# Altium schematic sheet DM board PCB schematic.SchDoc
size 386 x 246 mm
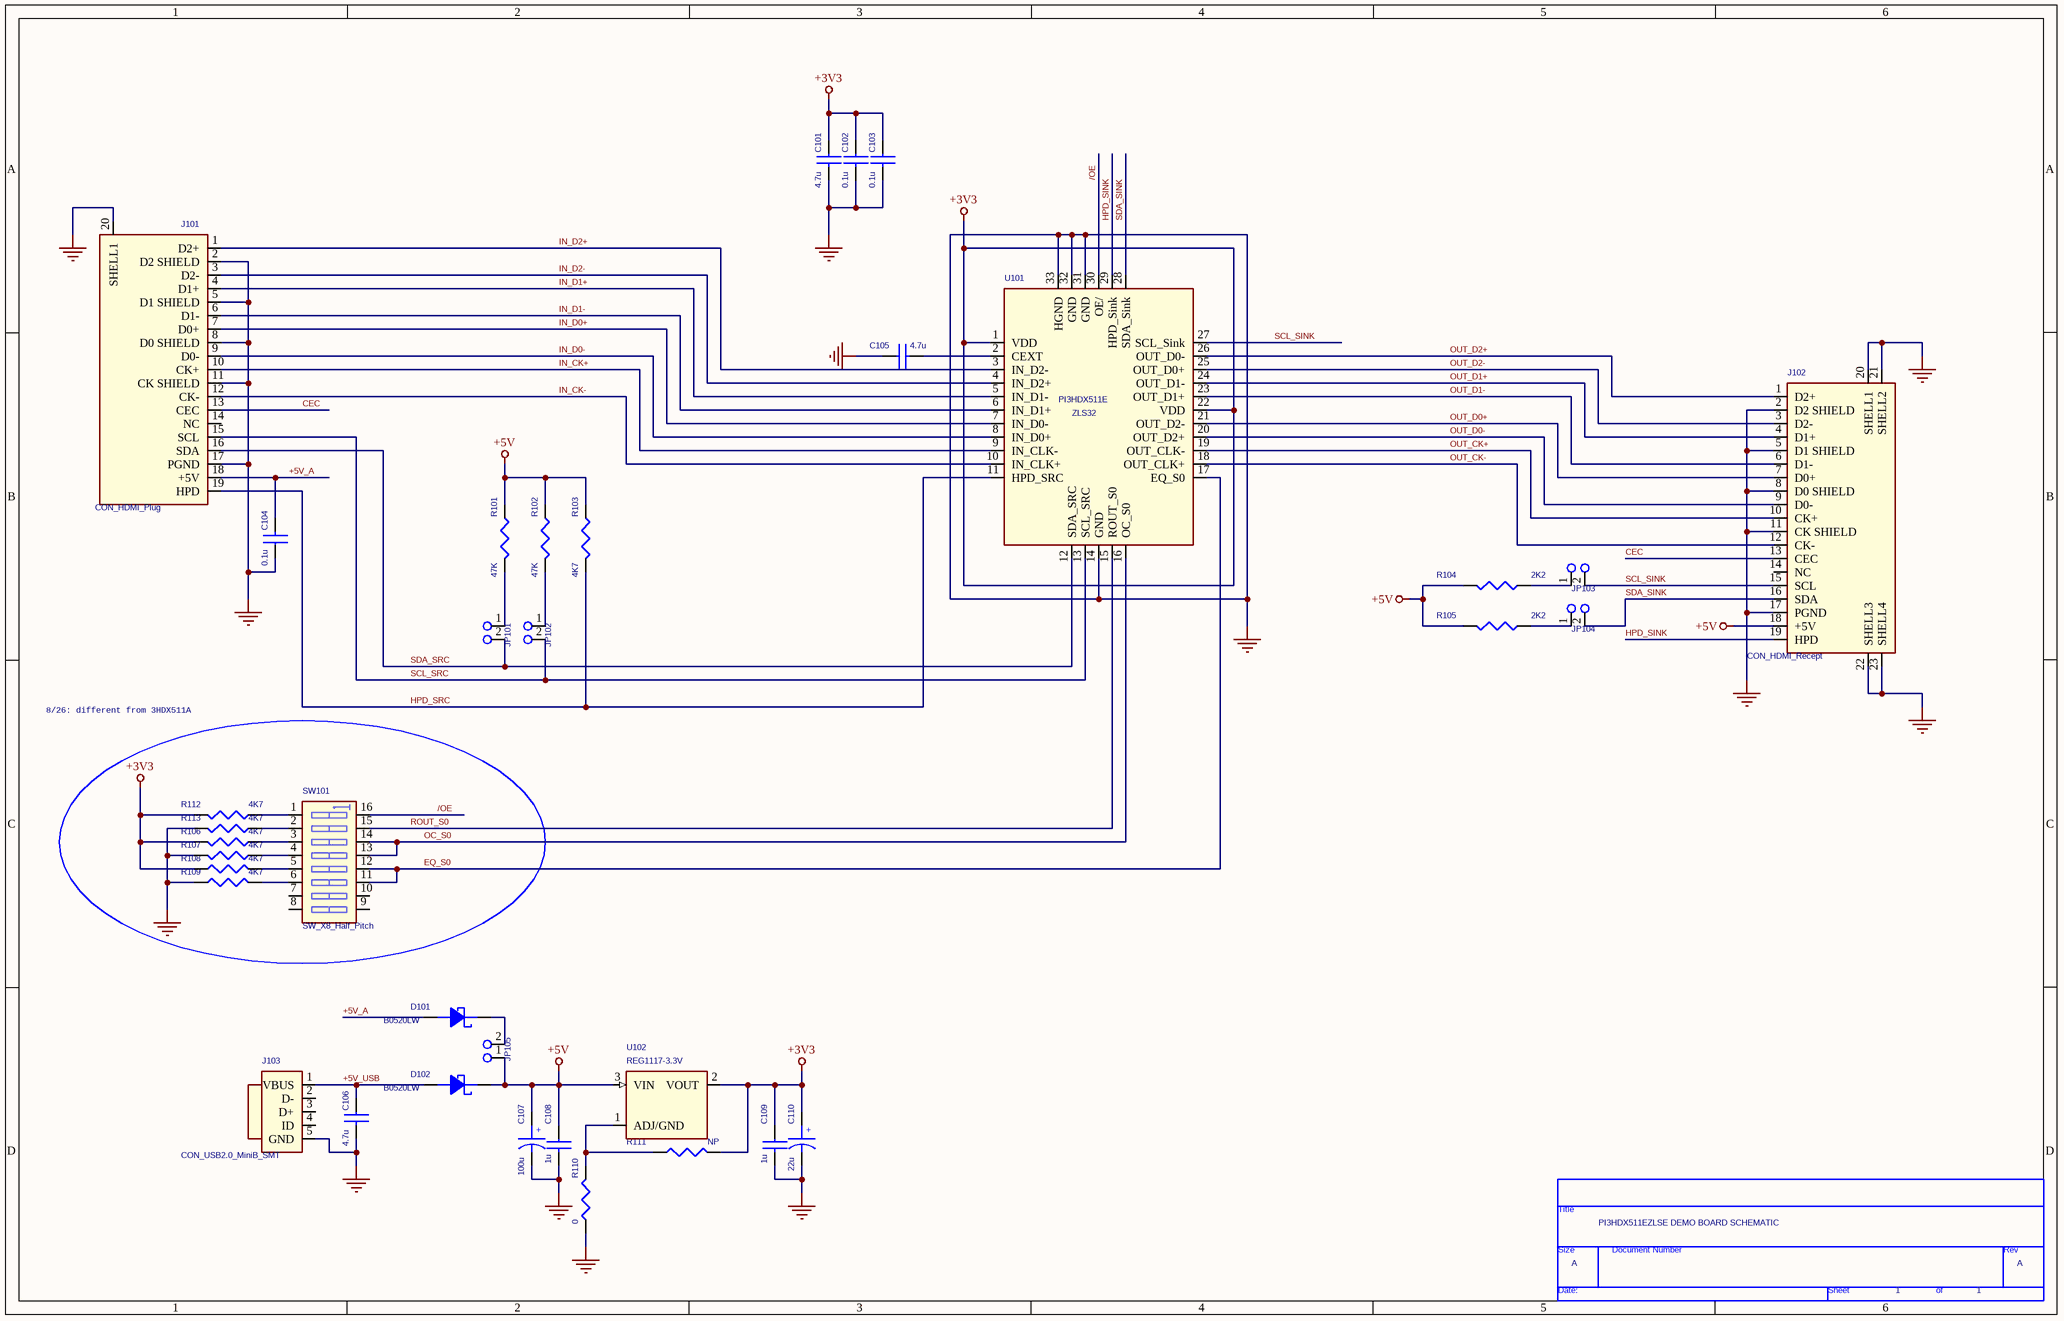
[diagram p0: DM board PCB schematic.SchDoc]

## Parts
*  RevCode: A  Title: PI3HDX511EZLSE DEMO BOARD SCHEMATIC  Page Number: 1  (hidden comment: TitleBlock0)  (graphical)
C101  4.7u  [CC_0805]
C102  0.1u  [CC_0402]
C103  0.1u  [CC_0402]
C104  0.1u  [CC_0402]
C105  4.7u  [CC_0805]
C106  4.7u  [CAP@CC_0805]
C107  100u  [CAP@CT_7343]
C108  1u  [CAP@CC_0805]
C109  1u  [CAP@CC_0805]
C110  22u  [CAP@CT_3528]
D101  B0520LW  [D@SOD-123]
D102  B0520LW  [D@SOD-123]
J101  CON_HDMI_Plug  [CON_HDMI_Plug]
J102  CON_HDMI_Recept  [CON_HDMI_Recept]
J103  CON_USB2.0_MiniB_SMT  [CON_USB2.0_MiniB_SMT]
JP101  2x1 Pin Header  [2x1 Pin Header]  (value not drawn)
JP102  2x1 Pin Header  [2x1 Pin Header]  (value not drawn)
JP103  2x1 Pin Header  [2x1 Pin Header]  (value not drawn)
JP104  2x1 Pin Header  [2x1 Pin Header]  (value not drawn)
JP105  2x1 Pin Header  [2x1 Pin Header]  (value not drawn)
R101  47K  [R_0402]
R102  47K  [R_0402]
R103  4K7  [R_0402]
R104  2K2  [R_0402]
R105  2K2  [R_0402]
R106  4K7  [R_0402]
R107  4K7  [R_0402]
R108  4K7  [R_0402]
R109  4K7  [R_0402]
R110  0  [RES@R_0402]
R111  NP  [RES@R_0402]
R112  4K7  [R_0402]
R113  4K7  [R_0402]
SW101  SW_X8_Half_Pitch  [SW_X8_Half_Pitch]
U101  PI3HDX511E  [TQFN32_3X6]
U102  REG1117-3.3V  [Pow_SOT_89]

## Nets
+3V3: C101.1 C102.1 C103.1 C109.1 C110.1 R106.2 R108.1 R111.2 R112.2 U101.1(VDD) U101.22(VDD) U102.2(VOUT)
+5V: C107.1 C108.1 D102.2 J102.18(+5V) JP105.1 R101.1 R102.1 R103.1 R104.2 R105.2 U102.3(VIN)
GND: C101.2 C102.2 C103.2 C104.1 C105.1 C106.2 C107.2 C108.2 C109.2 C110.2 J101.2(D2_SHIELD) J101.5(D1_SHIELD) J101.8(D0_SHIELD) J101.11(CK_SHIELD) J101.17(PGND) J101.20(SHELL1) J102.2(D2_SHIELD) J102.5(D1_SHIELD) J102.8(D0_SHIELD) J102.11(CK_SHIELD) J102.17(PGND) J102.20(SHELL1) J102.21(SHELL2) J102.22(SHELL3) J102.23(SHELL4) J103.5(GND) R107.2 R109.1 R110.1 R113.2 U101.14(GND) U101.31(GND) U101.32(GND) U101.33(HGND)
+5V_A: C104.2 D101.1 J101.18(+5V)
+5V_USB: C106.1 D102.1 J103.1(VBUS)
/OE: SW101.16(B1) U101.30(OE/)
CEC: J101.13(CEC) J102.13(CEC)
EQ_S0: SW101.11(B6) SW101.12(B5) U101.17(EQ_S0)
HPD_SINK: J102.19(HPD) U101.29(HPD_Sink)
HPD_SRC: J101.19(HPD) R103.2 U101.11(HPD_SRC)
IN_CK+: J101.10(CK+) U101.9(IN_CLK-)
IN_CK-: J101.12(CK-) U101.10(IN_CLK+)
IN_D0+: J101.7(D0+) U101.7(IN_D0-)
IN_D0-: J101.9(D0-) U101.8(IN_D0+)
IN_D1+: J101.4(D1+) U101.5(IN_D1-)
IN_D1-: J101.6(D1-) U101.6(IN_D1+)
IN_D2+: J101.1(D2+) U101.3(IN_D2-)
IN_D2-: J101.3(D2-) U101.4(IN_D2+)
OC_S0: SW101.13(B4) SW101.14(B3) U101.16(OC_S0)
OUT_CK+: J102.10(CK+) U101.19(OUT_CLK-)
OUT_CK-: J102.12(CK-) U101.18(OUT_CLK+)
OUT_D0+: J102.7(D0+) U101.21(OUT_D2-)
OUT_D0-: J102.9(D0-) U101.20(OUT_D2+)
OUT_D1+: J102.4(D1+) U101.24(OUT_D1-)
OUT_D1-: J102.6(D1-) U101.23(OUT_D1+)
OUT_D2+: J102.1(D2+) U101.26(OUT_D0-)
OUT_D2-: J102.3(D2-) U101.25(OUT_D0+)
ROUT_S0: SW101.15(B2) U101.15(ROUT_S0)
SCL_SINK: J102.15(SCL) JP103.2 U101.27(SCL_Sink)
SCL_SRC: J101.15(SCL) JP102.2 U101.13(SCL_SRC)
SDA_SINK: J102.16(SDA) JP104.2 U101.28(SDA_Sink)
SDA_SRC: J101.16(SDA) JP101.2 U101.12(SDA_SRC)
NetC105_2: C105.2 U101.2(CEXT)
NetD101_2: D101.2 JP105.2
NetJP101_1: JP101.1 R101.2
NetJP102_1: JP102.1 R102.2
NetJP103_1: JP103.1 R104.1
NetJP104_1: JP104.1 R105.1
NetR106_1: R106.1 SW101.3(A3)
NetR107_1: R107.1 SW101.4(A4)
NetR108_2: R108.2 SW101.5(A5)
NetR109_2: R109.2 SW101.6(A6)
NetR110_2: R110.2 R111.1 U102.1(ADJ/GND)
NetR112_1: R112.1 SW101.1(A1)
NetR113_1: R113.1 SW101.2(A2)

Not connected (* = marked no-connect by the designer): J101 14(NC); J102 14(NC); J103 2(D-) 3(D+) 4(ID); SW101 7(A7) 8(A8) 9(B8) 10(B7)

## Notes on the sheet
- (near U101) ZLS32
- 8/26: different from 3HDX511A

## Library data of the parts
* = TitleBlock0: Doc: PI3VDP411LS
C101-C103 = C_0.1u_0402
C104 = C_10n_0402
C105 = C_4.7u_0805
C106 C108 C109 = CHIP CAP0805
C107 = 100UF 7343_1
C110 = 22UF 3528
D101 D102 = SchottkyDiode@SOD-123_1
R101-R109 R112 R113 = R_0402
R110 R111 = CHIP RES0402_1
U101 = PI3VDP411LSZDE@TQFN48_6
U102 = REG1117ADJ@SOT89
